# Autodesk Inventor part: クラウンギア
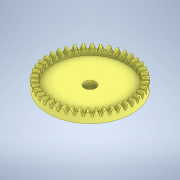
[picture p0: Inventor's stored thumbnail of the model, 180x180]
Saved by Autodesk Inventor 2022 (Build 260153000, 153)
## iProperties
Created: 2024-11
Part Number: クラウンギア
Material: 一般
Document SubType Name: Modeling
Designer: jsat7
Density: 1 g/cm^3
Appearance: 既定
Author: jsat7
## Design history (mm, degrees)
sketch "スケッチ1"
  geometry: L1 (0, 0)-(-16.481, 0); L2 (0, 0)-(-15.194, -0.569); L3 (0, 0)-(-15.177, 0.568); C1 r 9.5 at (0, 0); A1 r 11 centre (0, 0) between (-10.992, 0.411) and (-10.992, -0.411); 1 further point
  constraints: 6 end point, 2 centre point, 2 coincident, 2 point on circle, 2 point on line, 1 horizontal
  dimensions: "d0" = 22 diameter of A1; "d1" = 19 diameter of C1; "d2" = 2.14286 deg angle of L1 L2; "d3" = 2.14286 deg angle of L3 L1 (= d2)
sketch "スケッチ2"
  geometry: 1 further point
node "作業平面1"
sketch "スケッチ3"
  geometry: L1 (0.515, 0)-(0.291, 0) reference; L2 (0.5, 0.6)-(0.5, 0); L3 (0.5, -0.6)-(0.5, 0); L4 (0, 0.151)-(0, -0.212) reference; L5 (0.5, 0.6)-(0, 0.411); L6 (0, 0.411)-(-0.625, 0.175); L7 (0.5, -0.6)-(0, -0.411); L8 (0, -0.411)-(-0.625, -0.175); L9 (-0.625, 0.175)-(-0.625, -0.175); C1 r 0.002 at (0, 0.411); C2 r 0.002 at (0, -0.411); 5 further points
  constraints: 18 end point, 4 point on line, 3 vertical, 2 centre point, 2 horizontal, 1 collinear, 1 perpendicular, 2 other
  dimensions: "d5" = 0.00409 diameter of C1; "d6" = 0.6 distance from line of L1 L2.start; "d7" = 0.6 distance from line of L1 L3.start; "d8" = 0.5 distance between parallel lines of L4 L2; "d9" = 0.625 distance between parallel lines of L9 L4
extrude "押し出し1" new body sketch "スケッチ1" distance "d10" = 0.5; taper "d12" = 0 deg; dims "d11" = 2.125, "d13" = 0
extrude "押し出し2" cut sketch "スケッチ3" distance "d14" = 2; taper "d15" = 0 deg
node "作業平面2"
sketch "スケッチ4"
  geometry: C1 r 9.5 at (0, 0); 1 further point
  constraints: 1 centre point, 1 coincident
extrude "押し出し3" join sketch "スケッチ4" distance "d17" = 1; taper "d18" = 0 deg
sketch "スケッチ5"
  geometry: C1 r 1.5 at (0, 0); 1 further point
  constraints: 1 centre point, 1 coincident
  dimensions: "d22" = 3 diameter of C1
extrude "押し出し4" cut sketch "スケッチ5" distance "d23" = 1; taper "d24" = 0 deg
sketch "スケッチ6"
  geometry: C1 r 1.5 at (0, 0) reference; C2 r 2.4 at (0, 0); C3 r 1.5 at (0, 0); 1 further point
  constraints: 2 centre point, 2 coincident, 1 concentric
  dimensions: "d25" = 4.8 diameter of C2
extrude "押し出し5" join sketch "スケッチ6" distance "d26" = 2.9; taper "d27" = 0 deg
sketch "スケッチ7"
  geometry: 1 further point
node "ソリッド1"
pattern_circular "円形状パターン1" dims angle "d20" = 360 deg
other parameters: "d4" = 11, "d16" = 0
